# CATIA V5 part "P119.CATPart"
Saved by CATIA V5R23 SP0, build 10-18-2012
Part number: P119
Definition: Vis Chc M8x30
Description: ISO 4762 Vis Chc M8x30
Publications: "Mating Edge", "Axis"
Bounding box of the stored display mesh (mm): x -30 to 8, y -6.5 to 6.5, z -6.453 to 6.453
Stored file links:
  C:\wamp\www\COURS\CONCEPTION GMP1\TITRE 02-SEMESTRE 2\03-TP7-PRESSE MECANIQUE\eleve\P119.CATPart
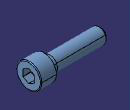
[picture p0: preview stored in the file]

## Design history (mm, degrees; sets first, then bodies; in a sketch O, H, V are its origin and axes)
Parameters
  Material = "St"
  d_dia = 8 mm
  l_nom = 30 mm
  k_head_depth_max = 8 mm
  s_nom = 6 mm
  r_min = 0.4 mm
  ds_max = 8 mm
  e = 6.86 mm
  t_min = 4 mm
  p_pitch = 1.25 mm
  Threading = 26.875 mm
  dk_max = 13 mm
  PartNumber = "ISO 4762 Vis Chc M8x30"
Body1 "PartBody" (main body)
  Sketch1 on yz-plane, origin (0, 0, 0), H (0, 1, 0), V (0, 0, 1)
    circle A1 centre (0, 0) radius 6.5
    radius A1 = 6.5 {= dk_max /2}
  Pad1: profile Sketch1, direction (1, 0, 0), length 8 {= k_head_depth_max}
  Fillet1: radius 0.4 {= r_min}, on edge [face of Pad1 | face of Pad1]
  Body2
    Sketch2 on face of Pad1, origin (8, 0, 0), H (0, 1, 0), V (0, 0, 1)
      point P1 (3, -1.7321)
      point P2 (3, 1.7321)
      point P3 (0, 3.4641)
      point P4 (-3, 1.7321)
      point P5 (-3, -1.7321)
      point P6 (0, -3.4641)
      point P7 (3, 0)
      line L1 (3, -1.7321) -> (3, 1.7321)
      line L2 (3, 1.7321) -> (0, 3.4641)
      line L3 (0, 3.4641) -> (-3, 1.7321)
      line L4 (-3, 1.7321) -> (-3, -1.7321)
      line L5 (-3, -1.7321) -> (0, -3.4641)
      line L6 (0, -3.4641) -> (3, -1.7321)
      construction line L7 (0, 0) -> (3, 0)
      construction circle A1 centre (0, 0) radius 3.4641
      construction arc A2 centre (-3, -1.7321) radius 3.4641 from (-3, 1.7321) to (0, -3.4641) cw
      construction arc A3 centre (3, 1.7321) radius 3.4641 from (0, 3.4641) to (3, -1.7321) ccw
      point P8 (-3, -1.7321)
      point P9 (3, 1.7321)
      distance L1 L4 = 6 {= s_nom}
      horizontal: L7 H
      coincidence: A1 P1, A1 P2, A1 P3, A1 P4, A1 P5, A1 P6, A2 P4, A2 P6, A2 O, P8 P5, A3 P3, A3 P1, A3 O, P9 P2
      midpoint: P7 L1
    Pad2: profile Sketch2, direction (-1, 0, 0), length 5.9769 {= t_min +(e /3.47)}
    Body3
      Sketch3 on zx-plane, origin (0, 0, 0), H (-1, 0, 0), V (0, 0, 1)
        point P1 (-2.0197, 0)
        line L1 (-2.0197, 0) -> (-4, 3.43)
        line L2 (-4, 3.43) -> (-8, 3.43)
        line L3 (-8, 3.43) -> (-8, 0)
        axis line L4 (-46.2384, 0) -> (26.3409, 0)
        reference projected line E1 (-8, -6.9227) -> (-8, 6.9227) from edge [face of Pad2 | face of Pad2]
        length L2 = 4 {= t_min}
        angle L1 L4 = 60
        distance L2 L4 = 3.43 {= e /2}
        horizontal: L2 H, L4 H
        perpendicularity: L3 L2
        fix: L4
        coincidence: L3 E1, P1 L4
      Shaft1: profile Sketch3, axis Sketch3.L4, angle 360
    Intersect1: tool Body3
  Remove1: tool Body2
  Sketch4 on xy-plane, origin (0, 0, 0), H (1, 0, 0), V (0, 1, 0)
    line L1 (0, 0) -> (0, 4)
    line L2 (0, 4) -> (-3.125, 4)
    line L3 (-3.125, 4) -> (-3.125, 3.9024)
    line L4 (-3.125, 3.9024) -> (-30, 3.9024)
    line L5 (-30, 3.9024) -> (-30, 0)
    axis line L6 (-192.3446, 0) -> (99.1594, 0)
    distance L5 L1 = 30 {= l_nom}
    distance L3 L5 = 26.875 {= Threading}
    distance L2 L6 = 4 {= ds_max /2}
    distance L4 L6 = 3.9024 {= d_dia /2.05}
    vertical: L1 V, L3 V, L5 V
    horizontal: L2 H, L4 H, L6 H
    fix: L6
  Shaft2: profile Sketch4, axis Sketch4.L6, angle 360
  Fillet2: radius 0.4 {= r_min}, on edge [face of Shaft2 | face of Pad1]
  Chamfer1: length 1.25 {= p_pitch}, angle 45, on edge [face of Shaft2 | face of Shaft2]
